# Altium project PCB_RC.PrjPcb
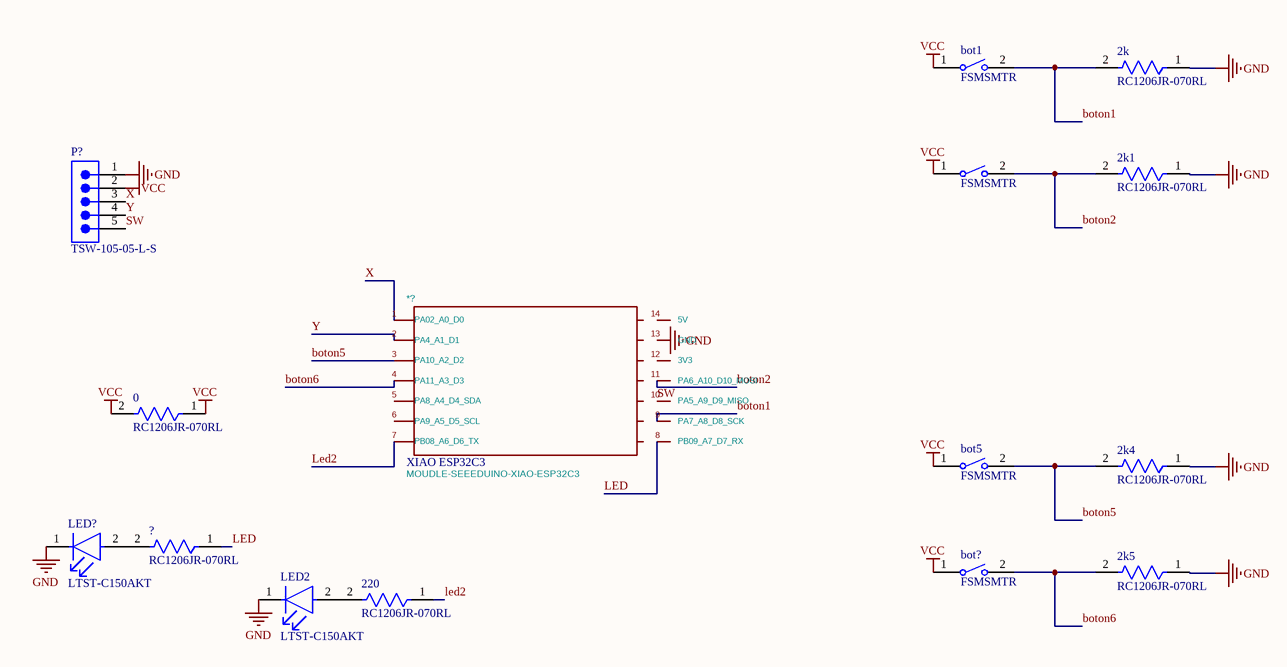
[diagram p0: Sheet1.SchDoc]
1 sheet, 15 parts. Net scope: global (net labels, ports and power ports of the same name join across sheets).
Board file: PCB1.PcbDoc

## Sheet Sheet1.SchDoc
size A4; SheetNumber: 1; SheetTotal: 1

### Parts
(Parts that share a designator on the sheet are numbered #1, #2 ... from top to bottom, then left to right.)
0  RC1206JR-070RL  [FP-RC1206-MFG]
2k  RC1206JR-070RL  [FP-RC1206-MFG]
2k1  RC1206JR-070RL  [FP-RC1206-MFG]
2k4  RC1206JR-070RL  [FP-RC1206-MFG]
2k5  RC1206JR-070RL  [FP-RC1206-MFG]
220  RC1206JR-070RL  [FP-RC1206-MFG]
*?  XIAO ESP32C3  value MOUDLE-SEEEDUINO-XIAO-ESP32C3  [MOUDLE14P-SMD-2.54-21X17.8MM]
?#1  FSMSMTR  [TECO-FSMSMTR_V]
?#2  RC1206JR-070RL  [FP-RC1206-MFG]
bot1  FSMSMTR  [TECO-FSMSMTR_V]
bot5  FSMSMTR  [TECO-FSMSMTR_V]
bot?  FSMSMTR  [TECO-FSMSMTR_V]
LED2  LTST-C150AKT  [FP-LTST-C150AKT-MFG]
LED?  LTST-C150AKT  [FP-LTST-C150AKT-MFG]
P?  TSW-105-05-L-S  [SMTC-TSW-105-05-X-S]

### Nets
GND: 2k.1 2k1.1 2k4.1 2k5.1 *?.13(GND) LED2.1(C) LED?.1(C) P?.1
VCC: 0.1 0.2 ?#1.1 bot1.1 bot5.1 bot?.1 P?.2
boton1: 2k.2 *?.9(PA7_A8_D8_SCK) bot1.2
boton2: 2k1.2 *?.11(PA6_A10_D10_MOSI) ?#1.2
boton5: 2k4.2 *?.3(PA10_A2_D2) bot5.2
boton6: 2k5.2 *?.4(PA11_A3_D3) bot?.2
LED: *?.8(PB09_A7_D7_RX) ?#2.1
Led2: 220.1 *?.7(PB08_A6_D6_TX)
SW: *?.10(PA5_A9_D9_MISO) P?.5
X: *?.1(PA02_A0_D0) P?.3
Y: *?.2(PA4_A1_D1) P?.4
Net220_2: 220.2 LED2.2(A)
Net?#2_2: ?#2.2 LED?.2(A)

Not connected (* = marked no-connect by the designer): *? 5(PA8_A4_D4_SDA) 6(PA9_A5_D5_SCL) 12(3V3) 14(5V)

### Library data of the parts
0 2k 2k1 2k4 2k5 220 ?#2 = CMP-2100-03681-2: RES SMD 0 OHM JUMPER 1/4W 1206; Manufacturer: YAGEO; Voltage Rating: 200V; Temperature Coefficient: 300ppm/°C; Power Rating: 0.25W; Value: 0Ω; Tolerance: 5%
*? = MOUDLE-SEEEDUINO-XIAO-ESP32C3
?#1 bot1 bot5 bot? = CMP-2000-07501-1: FSMSM Push Button Switch, 50 mA, -35 to 85 degC, 2-Pin SMD, RoHS, Tape and Reel; Manufacturer: TE Connectivity; Voltage Rating (DC): 24V; Electrical Life: 20000Cycles; Operating Force: 180gf; Switch Travel: 0.25mm; Contact Current Rating: 50mA; Case\/Package: SMD/SMT; Actuator Length: 1.07mm; Throw Configuration: SPST; Actuator Material: Polyamide; Contact Resistance: 100mOhm; Illumination Type: Illuminated; Max Voltage Rating (DC): 12V
LED2 LED? = CMP-22017-000004-1: LED AMBER CLEAR SMD; Manufacturer: Lite-On; Luminous Intensity: 6mcd; Viewing Angle: 130°; Wavelength: 602nm; Reverse Voltage: 5V; Forward Current: 30mA; Led Orientation: Top View; Power Dissipation: 100mW; Peak Emmision Wavelength: 610nm; Forward Voltage: 2.1V
P? = CMP-1024-00366-1: 0.025" SQ Post Header, Through-hole, Vertical, -55 to 125 degC, 2.54 mm Pitch, 5-Pin, Male, RoHS; Manufacturer: Samtec; Pitch: 2.54 mm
